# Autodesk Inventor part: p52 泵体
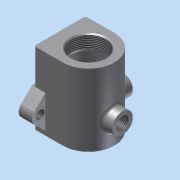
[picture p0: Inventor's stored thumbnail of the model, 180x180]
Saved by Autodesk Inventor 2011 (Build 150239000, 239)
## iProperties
Created: 2014-01
Part Number: p52 泵体
Document SubType Name: Modeling
Designer: Administrator
Density: 1 g/cm^3
Author: Administrator
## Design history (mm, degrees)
sketch "草图1"
  geometry: L1 (0, -25)-(-28, -25); L2 (-28, -25)-(-28, 25); L3 (-28, 25)-(0, 25); A1 r 25 centre (0, 0) between (0, -25) and (0, 25); 1 further point
  constraints: 6 end point, 2 point on circle, 2 tangent, 1 centre point, 1 coincident, 1 horizontal, 1 perpendicular
  dimensions: "d0" = 50 diameter of A1; "d1" = 28 distance of L1.start L1.end
extrude "拉伸1" new body sketch "草图1" distance "d2" = 70; taper "d3" = 0 deg
hole "Hole1" diameter "d6" = 33.376; stored, may be unused: countersink angle "d10" = 90 deg, drill point angle "d12" = 0 deg; dims "d4" = 10, "d5" = 10, "d7" = 15, "d8" = 4, "d9" = 2, "d11" = 15
chamfer "倒角1" distance "d13" = 1; stored, may be unused: second distance "d14" = 2, angle "d15" = 45 deg
hole "Hole2" diameter "d18" = 20; stored, may be unused: countersink angle "d22" = 90 deg, drill point angle "d24" = 0 deg; dims "d16" = 10, "d17" = 10, "d19" = 15, "d20" = 36, "d21" = 42, "d23" = 45
node "工作平面1"
sketch "草图2"
  geometry: L1 (-25, 70)-(25, 70) reference; L2 (25, 0)-(25, 70) reference; L3 (25, 0)-(-25, 0) reference; L4 (-25, 0)-(-25, 70) reference; L5 (-30, 28)-(-30, 12); L6 (-18, 36)-(-25, 36); L7 (-18, 4)-(-25, 4); L8 (-18, 36)-(-18, -2.76); L9 (-25, 20)-(-38, 20); L10 (-25, 36)-(-34.951, 26.284); L11 (-25, 4)-(-35.571, 14.259); A1 r 8 centre (-30, 20) between (-34.951, 26.284) and (-35.571, 14.259); 1 further point
  constraints: 14 end point, 5 point on line, 3 parallel, 3 point on circle, 2 perpendicular, 1 centre point, 1 midpoint, 1 tangent
  dimensions: "d26" = 30 distance from line of point (0, 0) L5; "d28" = 16 diameter of A1; "d31" = 18 distance from line of point (0, 0) L8
extrude "拉伸2" join sketch "草图2" distance "d32" = 13; taper "d33" = 0 deg
hole "Hole3" diameter "d36" = 8.376; stored, may be unused: countersink angle "d40" = 90 deg, drill point angle "d42" = 118 deg; dims "d34" = 10, "d35" = 10, "d37" = 15, "d38" = 36, "d39" = 42, "d41" = 45
mirror "镜像1"
node "工作平面2"
sketch "草图3"
  geometry: L1 (25, 70)-(-25, 70) reference; L2 (-25, 0)-(-25, 70) reference; L3 (-25, 0)-(25, 0) reference; L4 (25, 0)-(25, 70) reference; C1 r 10 at (0, 23); 1 further point
  constraints: 1 centre point
  dimensions: "d44" = 20 diameter of C1; "d45" = 47 distance from line of C1.centre L1
extrude "拉伸3" join sketch "草图3" stored distance "d46" = 13; taper "d47" = 0 deg
hole "Hole4" diameter "d50" = 12.376; stored, may be unused: countersink angle "d54" = 90 deg, drill point angle "d56" = 0 deg; dims "d48" = 10, "d49" = 10, "d51" = 15, "d52" = 36, "d53" = 42, "d55" = 45
node "工作平面3"
sketch "草图4"
  geometry: L1 (28, 70)-(0, 70) reference; L2 (0, 0)-(28, 0) reference; L3 (0, 0)-(0, 70) reference; C1 r 10 at (0, 23)
  constraints: 1 centre point, 1 point on line
  dimensions: "d58" = 20 diameter of C1; "d59" = 47 distance from line of L1 C1.centre
extrude "拉伸4" join sketch "草图4" stored distance "d60" = 13; taper "d61" = 0 deg
hole "Hole5" diameter "d64" = 12.376; stored, may be unused: countersink angle "d68" = 90 deg, drill point angle "d70" = 0 deg; dims "d62" = 10, "d63" = 10, "d65" = 15, "d66" = 36, "d67" = 42, "d69" = 45
fillet "圆角1" dims "d71" = 3
fillet "圆角2" dims "d72" = 3
fillet "圆角4" dims "d74" = 3
fillet "圆角5" dims "d75" = 3
fillet "圆角6" dims "d76" = 3
fillet "圆角7" dims "d77" = 3
fillet "圆角8" dims "d78" = 3
fillet "圆角9" dims "d79" = 3
fillet "圆角10" dims "d80" = 2
node "实体1"
node "投影回路1"
node "投影回路2"
other parameters: "d29" = 16, "d30" = 16, "d43" = 33, "d57" = 33
